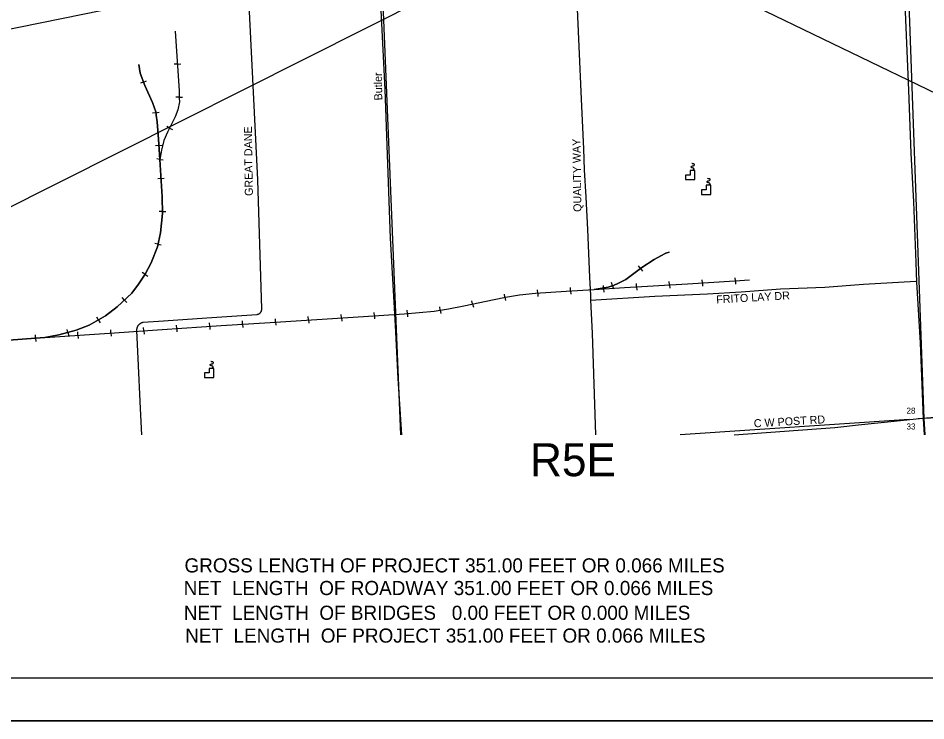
# Model space of a CAD drawing. Extents: x 646058 to 725608, y 1473014 to 1561048.
# Drawn here: x 671705 to 689850, y 1515181 to 1529228 of the extents above; entities that cross this region are included whole.
import ezdxf

# ---------------------------------------------------------------- set-up
doc = ezdxf.new("R2010")
doc.units = 0
for name, color, linetype in [('Default', 7, 'Continuous'), ('R_Border Notes', 7, 'Continuous'), ('R_Grid', 7, 'Continuous'), ('T_Vehicle Path Rt', 7, 'Continuous')]:
    doc.layers.add(name, color=color, linetype=linetype)

msp = doc.modelspace()

# ---------------------------------------------------------------- linework, layer by layer
at = {"layer": 'Default'}
for p, q in [((682592, 1531265), (666575, 1527988)), ((692696, 1526435), (682799, 1531230)), ((682805, 1531114), (666575, 1522951)), ((674889, 1528310), (674823, 1528305)), ((674889, 1528310), (674955, 1528314)), ((674211, 1527949), (674149, 1527926)), ((674211, 1527949), (674273, 1527972)), ((674924, 1527651), (674858, 1527651)), ((674924, 1527651), (674990, 1527651)), ((674457, 1527338), (674392, 1527326)), ((674457, 1527338), (674522, 1527349)), ((674733, 1527030), (674674, 1527060)), ((674733, 1527030), (674792, 1527000)), ((674517, 1526681), (674452, 1526676)), ((674517, 1526681), (674583, 1526686)), ((674540, 1526404), (674475, 1526414)), ((674540, 1526404), (674605, 1526394)), ((674561, 1526022), (674495, 1526019)), ((674561, 1526022), (674626, 1526026)), ((674591, 1525363), (674525, 1525361)), ((674591, 1525363), (674657, 1525366)), ((674499, 1524711), (674434, 1524725)), ((674499, 1524711), (674563, 1524697)), ((684143, 1524225), (684103, 1524278)), ((684143, 1524225), (684183, 1524172)), ((674238, 1524108), (674182, 1524143)), ((674238, 1524108), (674294, 1524072)), ((683408, 1523818), (683404, 1523883)), ((683586, 1523879), (683567, 1523942)), ((683586, 1523879), (683605, 1523816)), ((684067, 1523857), (684063, 1523923)), ((684726, 1523895), (684722, 1523961)), ((684726, 1523895), (684730, 1523830)), ((685384, 1523935), (685380, 1524000)), ((685384, 1523935), (685388, 1523869)), ((686043, 1523975), (686039, 1524040)), ((686043, 1523975), (686048, 1523909)), ((681436, 1523649), (681424, 1523713)), ((682091, 1523731), (682086, 1523797)), ((682091, 1523731), (682096, 1523666)), ((682749, 1523779), (682745, 1523845)), ((682749, 1523779), (682753, 1523713)), ((683408, 1523818), (683412, 1523752)), ((684067, 1523857), (684071, 1523791)), ((673830, 1523593), (673784, 1523641)), ((673830, 1523593), (673875, 1523545)), ((680790, 1523515), (680776, 1523580)), ((680790, 1523515), (680804, 1523451)), ((681436, 1523649), (681449, 1523584)), ((678827, 1523280), (678823, 1523346)), ((679485, 1523325), (679480, 1523391)), ((679485, 1523325), (679491, 1523259)), ((680142, 1523392), (680132, 1523457)), ((680142, 1523392), (680152, 1523326)), ((673308, 1523193), (673276, 1523251)), ((673308, 1523193), (673341, 1523136)), ((675534, 1523070), (675529, 1523136)), ((676192, 1523113), (676188, 1523179)), ((676851, 1523154), (676847, 1523220)), ((676851, 1523154), (676855, 1523088)), ((677510, 1523196), (677505, 1523262)), ((677510, 1523196), (677514, 1523130)), ((678168, 1523238), (678164, 1523304)), ((678168, 1523238), (678172, 1523172)), ((678827, 1523280), (678831, 1523215)), ((672701, 1522943), (672683, 1523007)), ((672900, 1522889), (672895, 1522955)), ((673558, 1522934), (673554, 1523000)), ((674217, 1522979), (674212, 1523045)), ((674217, 1522979), (674221, 1522913)), ((674875, 1523024), (674871, 1523090)), ((674875, 1523024), (674880, 1522959)), ((675534, 1523070), (675538, 1523004)), ((676192, 1523113), (676196, 1523047)), ((672052, 1522832), (672048, 1522898)), ((672052, 1522832), (672056, 1522766)), ((672701, 1522943), (672718, 1522879)), ((672900, 1522889), (672904, 1522823)), ((673558, 1522934), (673563, 1522868))]:
    msp.add_line(p, q, dxfattribs=at)
for points in [[(689359, 1531681), (689409, 1529988), (689503, 1527791), (689549, 1526529), (689604, 1525555), (689651, 1524340), (689662, 1523953)], [(689818, 1521225), (689435, 1531730)], [(678860, 1531400), (678885, 1530711), (679038, 1527802), (679143, 1524831), (679241, 1523084), (679297, 1522026), (679371, 1520895)], [(682797, 1531279), (682865, 1529988), (682866, 1529801), (682875, 1529559), (682915, 1528661), (682962, 1527605), (683004, 1526615), (683022, 1526196), (683053, 1525647), (683085, 1525003), (683127, 1524049), (683145, 1523682), (683149, 1523588)], [(678875, 1530985), (678885, 1530711), (679038, 1527802), (679143, 1524831), (679241, 1523084), (679297, 1522026), (679371, 1520895)], [(678938, 1530989), (679347, 1520895)], [(674179, 1520895), (674151, 1521422), (674106, 1522424), (674078, 1522985), (674078, 1522991), (674078, 1522996), (674078, 1523002), (674078, 1523007), (674079, 1523012), (674080, 1523018), (674081, 1523023), (674082, 1523029), (674083, 1523034), (674085, 1523039), (674086, 1523044), (674088, 1523049), (674090, 1523055), (674092, 1523060), (674095, 1523064), (674097, 1523069), (674100, 1523074), (674103, 1523079), (674106, 1523083), (674109, 1523088), (674112, 1523092), (674116, 1523096), (674119, 1523100), (674123, 1523104), (674127, 1523108), (674131, 1523112), (674135, 1523116), (674139, 1523119), (674143, 1523122), (674148, 1523125), (674152, 1523128), (674157, 1523131), (674162, 1523134), (674167, 1523136), (674172, 1523139), (674177, 1523141), (674182, 1523143), (674187, 1523145), (674192, 1523146), (674197, 1523148), (674203, 1523149), (674612, 1523179), (675476, 1523239), (676478, 1523306), (676481, 1523307), (676485, 1523307), (676488, 1523308), (676492, 1523308), (676495, 1523309), (676499, 1523310), (676502, 1523311), (676505, 1523312), (676509, 1523313), (676512, 1523315), (676515, 1523316), (676519, 1523318), (676522, 1523320), (676525, 1523321), (676528, 1523323), (676531, 1523325), (676534, 1523328), (676536, 1523330), (676539, 1523332), (676542, 1523335), (676544, 1523337), (676547, 1523340), (676549, 1523342), (676551, 1523345), (676554, 1523348), (676556, 1523351), (676558, 1523354), (676560, 1523357), (676561, 1523360), (676563, 1523363), (676565, 1523366), (676566, 1523370), (676567, 1523373), (676569, 1523376), (676570, 1523380), (676571, 1523383), (676571, 1523387), (676572, 1523390), (676573, 1523394), (676573, 1523397), (676574, 1523401), (676574, 1523405), (676574, 1523408), (676574, 1523412), (676574, 1523415), (676495, 1525998), (676253, 1530847)], [(674846, 1528968), (674924, 1527774), (674924, 1527631), (674928, 1527553), (674896, 1527393), (674846, 1527254), (674691, 1526948), (674617, 1526780), (674568, 1526592), (674540, 1526404)], [(674846, 1528968), (674924, 1527774), (674924, 1527631), (674928, 1527553), (674896, 1527393), (674846, 1527254), (674691, 1526948), (674617, 1526780), (674568, 1526592), (674540, 1526404)], [(674846, 1528968), (674924, 1527774), (674924, 1527631), (674928, 1527553), (674896, 1527393), (674846, 1527254), (674691, 1526948), (674617, 1526780), (674568, 1526592), (674540, 1526404)], [(671433, 1522786), (671873, 1522820), (672241, 1522845), (672519, 1522894), (672867, 1522988), (673125, 1523090), (673452, 1523274), (673685, 1523454), (673975, 1523732), (674110, 1523908), (674241, 1524113), (674364, 1524334), (674487, 1524657), (674548, 1524935), (674593, 1525324), (674581, 1525655), (674540, 1526404), (674507, 1526809), (674482, 1527156), (674466, 1527287), (674454, 1527357), (674393, 1527541), (674237, 1527880), (674143, 1528130), (674114, 1528302)], [(674114, 1528302), (674143, 1528130), (674237, 1527880), (674393, 1527541), (674454, 1527357), (674466, 1527287), (674482, 1527156), (674507, 1526809), (674540, 1526404), (674581, 1525655), (674593, 1525324), (674548, 1524935), (674487, 1524657), (674364, 1524334), (674241, 1524113), (674110, 1523908), (673975, 1523732), (673685, 1523454), (673452, 1523274), (673125, 1523090), (672867, 1522988), (672519, 1522894), (672241, 1522845), (671873, 1522820)], [(671873, 1522820), (672241, 1522845), (672519, 1522894), (672867, 1522988), (673125, 1523090), (673452, 1523274), (673685, 1523454), (673975, 1523732), (674110, 1523908), (674241, 1524113), (674364, 1524334), (674487, 1524657), (674548, 1524935), (674593, 1525324), (674581, 1525655), (674540, 1526404), (674507, 1526809), (674482, 1527156), (674466, 1527287), (674454, 1527357), (674393, 1527541), (674237, 1527880), (674143, 1528130), (674114, 1528302)], [(685186, 1526186), (685187, 1526188), (685187, 1526189), (685189, 1526191), (685190, 1526192), (685191, 1526193), (685192, 1526194), (685193, 1526195), (685194, 1526195), (685197, 1526197), (685199, 1526198), (685201, 1526198), (685205, 1526199), (685209, 1526201), (685213, 1526203), (685215, 1526206), (685217, 1526210), (685217, 1526214), (685215, 1526218), (685212, 1526223), (685204, 1526229), (685196, 1526232), (685186, 1526235), (685180, 1526237), (685175, 1526237), (685169, 1526238), (685163, 1526242), (685158, 1526247), (685157, 1526253), (685159, 1526258), (685163, 1526263), (685168, 1526268), (685175, 1526271), (685186, 1526274), (685195, 1526276), (685204, 1526278), (685210, 1526279), (685216, 1526283), (685221, 1526290), (685222, 1526297), (685222, 1526303), (685220, 1526307), (685213, 1526313), (685202, 1526315), (685195, 1526316), (685188, 1526316), (685177, 1526319), (685169, 1526323)], [(685186, 1526186), (685187, 1526188), (685187, 1526189), (685189, 1526191), (685190, 1526192), (685191, 1526193), (685192, 1526194), (685193, 1526195), (685194, 1526195), (685197, 1526197), (685199, 1526198), (685201, 1526198), (685205, 1526199), (685209, 1526201), (685213, 1526203), (685215, 1526206), (685217, 1526210), (685217, 1526214), (685215, 1526218), (685212, 1526223), (685204, 1526229), (685196, 1526232), (685186, 1526235), (685180, 1526237), (685175, 1526237), (685169, 1526238), (685163, 1526242), (685158, 1526247), (685157, 1526253), (685159, 1526258), (685163, 1526263), (685168, 1526268), (685175, 1526271), (685186, 1526274), (685195, 1526276), (685204, 1526278), (685210, 1526279), (685216, 1526283), (685221, 1526290), (685222, 1526297), (685222, 1526303), (685220, 1526307), (685213, 1526313), (685202, 1526315), (685195, 1526316), (685188, 1526316), (685177, 1526319), (685169, 1526323)], [(685504, 1525889), (685505, 1525890), (685506, 1525891), (685507, 1525893), (685508, 1525894), (685509, 1525895), (685510, 1525896), (685511, 1525897), (685513, 1525898), (685515, 1525899), (685518, 1525900), (685520, 1525901), (685523, 1525902), (685527, 1525903), (685531, 1525905), (685534, 1525908), (685535, 1525912), (685536, 1525917), (685534, 1525921), (685530, 1525926), (685522, 1525931), (685514, 1525935), (685505, 1525938), (685498, 1525939), (685493, 1525940), (685488, 1525941), (685481, 1525944), (685476, 1525949), (685475, 1525955), (685477, 1525961), (685481, 1525966), (685486, 1525970), (685493, 1525973), (685504, 1525976), (685513, 1525979), (685522, 1525980), (685528, 1525982), (685534, 1525986), (685539, 1525993), (685540, 1525999), (685540, 1526005), (685539, 1526010), (685531, 1526015), (685520, 1526018), (685513, 1526018), (685506, 1526019), (685495, 1526022), (685487, 1526026)], [(685504, 1525889), (685505, 1525890), (685506, 1525891), (685507, 1525893), (685508, 1525894), (685509, 1525895), (685510, 1525896), (685511, 1525897), (685513, 1525898), (685515, 1525899), (685518, 1525900), (685520, 1525901), (685523, 1525902), (685527, 1525903), (685531, 1525905), (685534, 1525908), (685535, 1525912), (685536, 1525917), (685534, 1525921), (685530, 1525926), (685522, 1525931), (685514, 1525935), (685505, 1525938), (685498, 1525939), (685493, 1525940), (685488, 1525941), (685481, 1525944), (685476, 1525949), (685475, 1525955), (685477, 1525961), (685481, 1525966), (685486, 1525970), (685493, 1525973), (685504, 1525976), (685513, 1525979), (685522, 1525980), (685528, 1525982), (685534, 1525986), (685539, 1525993), (685540, 1525999), (685540, 1526005), (685539, 1526010), (685531, 1526015), (685520, 1526018), (685513, 1526018), (685506, 1526019), (685495, 1526022), (685487, 1526026)], [(684716, 1524550), (684653, 1524527), (684552, 1524477), (684416, 1524401), (684170, 1524245), (684036, 1524144), (683855, 1524006), (683704, 1523928), (683606, 1523885), (683498, 1523852), (683218, 1523806)], [(684716, 1524550), (684653, 1524527), (684552, 1524477), (684416, 1524401), (684170, 1524245), (684036, 1524144), (683855, 1524006), (683704, 1523928), (683606, 1523885), (683498, 1523852), (683218, 1523806)], [(683218, 1523806), (683498, 1523852), (683606, 1523885), (683704, 1523928), (683855, 1524006), (684036, 1524144), (684170, 1524245), (684416, 1524401), (684552, 1524477), (684653, 1524527), (684716, 1524550)], [(672241, 1522845), (673632, 1522939), (674585, 1523004), (675763, 1523086), (676744, 1523147), (678609, 1523266), (679419, 1523319), (680020, 1523372), (680306, 1523417), (680617, 1523479), (681218, 1523606), (681447, 1523651), (681725, 1523696), (682048, 1523728), (682658, 1523773), (683218, 1523806), (683827, 1523843), (685087, 1523917), (686032, 1523974), (686322, 1523994)], [(672241, 1522845), (673632, 1522939), (674585, 1523004), (675763, 1523086), (676744, 1523147), (678609, 1523266), (679419, 1523319), (680020, 1523372), (680306, 1523417), (680617, 1523479), (681218, 1523606), (681447, 1523651), (681725, 1523696), (682048, 1523728), (682658, 1523773), (683218, 1523806), (683827, 1523843), (685087, 1523917), (686032, 1523974), (686322, 1523994)], [(672241, 1522845), (673632, 1522939), (674585, 1523004), (675763, 1523086), (676744, 1523147), (678609, 1523266), (679419, 1523319), (680020, 1523372), (680306, 1523417), (680617, 1523479), (681218, 1523606), (681447, 1523651), (681725, 1523696), (682048, 1523728), (682658, 1523773), (683218, 1523806), (683827, 1523843), (685087, 1523917), (686032, 1523974), (686322, 1523994)], [(683149, 1523588), (684431, 1523668), (685485, 1523720), (686156, 1523756), (686946, 1523820), (687828, 1523849), (688604, 1523911), (689653, 1523967)], [(689662, 1523953), (689735, 1522738), (689795, 1521216)], [(683149, 1523588), (683178, 1522929), (683246, 1520895)], [(668081, 1522557), (668340, 1522574), (669881, 1522676), (670774, 1522744), (671433, 1522786), (671873, 1522820)], [(671873, 1522820), (671433, 1522786), (670774, 1522744), (669881, 1522676), (668340, 1522574), (668081, 1522557)], [(675572, 1522229), (675572, 1522230), (675573, 1522232), (675574, 1522233), (675575, 1522235), (675576, 1522235), (675577, 1522236), (675579, 1522237), (675580, 1522238), (675583, 1522239), (675585, 1522240), (675587, 1522241), (675590, 1522242), (675594, 1522243), (675598, 1522245), (675601, 1522248), (675602, 1522252), (675603, 1522257), (675601, 1522261), (675597, 1522266), (675589, 1522271), (675582, 1522275), (675572, 1522278), (675565, 1522279), (675560, 1522280), (675555, 1522281), (675548, 1522284), (675544, 1522289), (675543, 1522295), (675544, 1522301), (675548, 1522306), (675553, 1522311), (675560, 1522314), (675571, 1522317), (675580, 1522319), (675589, 1522320), (675595, 1522322), (675601, 1522326), (675606, 1522333), (675608, 1522339), (675607, 1522345), (675606, 1522350), (675598, 1522355), (675587, 1522358), (675580, 1522358), (675573, 1522359), (675562, 1522362), (675554, 1522366)], [(675572, 1522229), (675572, 1522230), (675573, 1522232), (675574, 1522233), (675575, 1522235), (675576, 1522235), (675577, 1522236), (675579, 1522237), (675580, 1522238), (675583, 1522239), (675585, 1522240), (675587, 1522241), (675590, 1522242), (675594, 1522243), (675598, 1522245), (675601, 1522248), (675602, 1522252), (675603, 1522257), (675601, 1522261), (675597, 1522266), (675589, 1522271), (675582, 1522275), (675572, 1522278), (675565, 1522279), (675560, 1522280), (675555, 1522281), (675548, 1522284), (675544, 1522289), (675543, 1522295), (675544, 1522301), (675548, 1522306), (675553, 1522311), (675560, 1522314), (675571, 1522317), (675580, 1522319), (675589, 1522320), (675595, 1522322), (675601, 1522326), (675606, 1522333), (675608, 1522339), (675607, 1522345), (675606, 1522350), (675598, 1522355), (675587, 1522358), (675580, 1522358), (675573, 1522359), (675562, 1522362), (675554, 1522366)], [(692664, 1521374), (689818, 1521225)], [(689516, 1521205), (684942, 1520895)], [(686017, 1520895), (688029, 1521043), (688561, 1521106), (689219, 1521171), (689786, 1521229), (690434, 1521288)], [(689818, 1521225), (689697, 1521217)], [(689795, 1521216), (689814, 1520895)], [(689838, 1520895), (689818, 1521225)]]:
    msp.add_lwpolyline(points, dxfattribs=at)
for points in [[(685047, 1526000), (685230, 1526000), (685230, 1526184), (685139, 1526184), (685139, 1526092), (685047, 1526092)], [(685047, 1526000), (685230, 1526000), (685230, 1526184), (685139, 1526184), (685139, 1526092), (685047, 1526092)], [(685365, 1525703), (685549, 1525703), (685549, 1525886), (685457, 1525886), (685457, 1525795), (685365, 1525795)], [(685365, 1525703), (685549, 1525703), (685549, 1525886), (685457, 1525886), (685457, 1525795), (685365, 1525795)], [(675432, 1522043), (675616, 1522043), (675616, 1522226), (675524, 1522226), (675524, 1522135), (675432, 1522135)], [(675432, 1522043), (675616, 1522043), (675616, 1522226), (675524, 1522226), (675524, 1522135), (675432, 1522135)]]:
    msp.add_lwpolyline(points, close=True, dxfattribs=at)
at = {"layer": 'R_Border Notes'}
msp.add_line((716704, 1516037), (648725, 1516037), dxfattribs=at)
at = {"layer": 'T_Vehicle Path Rt'}
msp.add_line((646059, 1515182), (717726, 1515182), dxfattribs=at)
msp.add_lwpolyline([(646058, 1561048), (717726, 1561048), (717726, 1515181), (646058, 1515181)], close=True, dxfattribs=at)

# ---------------------------------------------------------------- texts
at = {"layer": 'Default'}
for s, rotation, p in [('Butler', 90.9014, (678984, 1527585)), ('GREAT DANE', 90.7966, (676397, 1525674)), ('QUALITY WAY', 90.7966, (682965, 1525356)), ('FRITO LAY DR', 3.3401, (685664, 1523522)), ('C W POST RD', 3.3401, (686416, 1521047))]:
    msp.add_text(s, height=160, rotation=rotation, dxfattribs=at).set_placement(p)
for s, height, p in [('28', 120, (689464, 1521322)), ('33', 120, (689464, 1521005)), ('R5E', 660, (681938, 1520071))]:
    msp.add_text(s, height=height, dxfattribs=at).set_placement(p)
at = {"layer": 'R_Grid'}
for s, p in [('GROSS LENGTH OF PROJECT 351.00 FEET OR 0.066 MILES', (675030, 1518147)), ('NET  LENGTH  OF ROADWAY 351.00 FEET OR 0.066 MILES', (675013, 1517695)), ('NET  LENGTH  OF BRIDGES   0.00 FEET OR 0.000 MILES', (675016, 1517200)), ('NET  LENGTH  OF PROJECT 351.00 FEET OR 0.066 MILES', (675044, 1516744))]:
    msp.add_text(s, height=282.73, dxfattribs=at).set_placement(p)

doc.saveas('drawing.dxf')
